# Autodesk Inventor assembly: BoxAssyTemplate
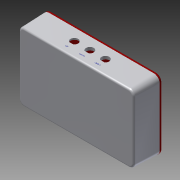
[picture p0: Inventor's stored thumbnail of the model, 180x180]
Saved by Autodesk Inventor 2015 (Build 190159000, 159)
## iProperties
Created: 2014-07
Part Number: BoxAssyTemplate
Document SubType Name: Assembly
Designer: Gavin
RuleStatus: InUse
Author: Gavin
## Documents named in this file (6)
- C:\Customer Folders\iLogic Demos\Normalisation\BoxAssyTemplate.iam
- C:\Customer Folders\iLogic Demos\Normalisation\BoxShell.ipt
- C:\Customer Folders\iLogic Demos\Normalisation\SealingStrip.ipt
- C:\Customer Folders\iLogic Demos\Normalisation\BoxLid.ipt
- C:\Users\Gavin\Documents\Inventor\Content Center Files\R2015\en-US\AS 1427(07)\AS 1427 - M8 x 20(6) II.ipt
- C:\Customer Folders\iLogic Demos\Normalisation\BoxSketch.ipt
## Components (8 placed, 5 different names)
1. BoxShell
2. SealingStrip
3. BoxLid
4. AS 1427 Z - Metric M8 x 20:1
5. AS 1427 Z - Metric M8 x 20:2
6. AS 1427 Z - Metric M8 x 20:3
7. AS 1427 Z - Metric M8 x 20:4
8. BoxSketch
## Named parameters: BoxDepth = 65 mm
